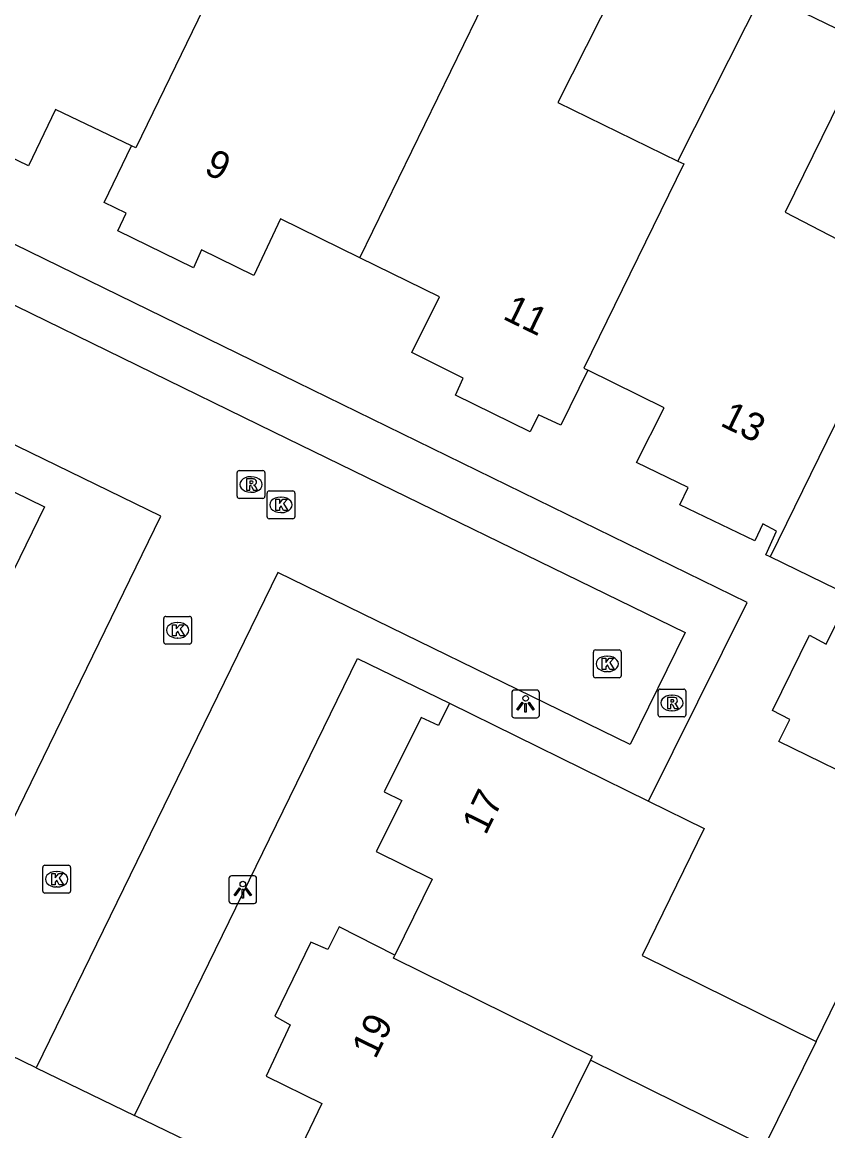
# Model space of a CAD drawing. Extents: x 159822 to 160765, y 380693 to 381634.
# Drawn here: x 160323.34 to 160352.34, y 381522.59 to 381562.51 of the extents above; entities that cross this region are included whole.
import ezdxf

# ---------------------------------------------------------------- set-up
doc = ezdxf.new("R2010")
doc.units = 0
for name, color, linetype in [('IMGEO_Kolk', 7, 'Continuous'), ('IMGEO_Lichtpunt', 7, 'Continuous'), ('IMGEO_Muur', 7, 'Continuous'), ('IMGEO_Pand', 7, 'Continuous'), ('IMGEO_Pand_nummerreeks', 7, 'Continuous'), ('IMGEO_Rijbaan_lokaal_open', 7, 'Continuous'), ('IMGEO_Rioolput', 7, 'Continuous'), ('IMGEO_Voetpad_open', 7, 'Continuous')]:
    doc.layers.add(name, color=color, linetype=linetype)

msp = doc.modelspace()

# ---------------------------------------------------------------- linework, layer by layer
at = {"layer": 'IMGEO_Kolk'}
for p, q in [((160332.157, 381544.701), (160332.157, 381545.553)), ((160332.232, 381545.627), (160333.084, 381545.627)), ((160333.158, 381545.553), (160333.158, 381544.701)), ((160332.645, 381545.407), (160332.67, 381545.407)), ((160332.668, 381544.847), (160332.643, 381544.847)), ((160333.084, 381544.627), (160332.232, 381544.627)), ((160328.513, 381541.112), (160329.365, 381541.112)), ((160328.438, 381540.186), (160328.438, 381541.038)), ((160328.926, 381540.892), (160328.951, 381540.892)), ((160329.439, 381541.038), (160329.439, 381540.186)), ((160328.949, 381540.332), (160328.924, 381540.332)), ((160329.365, 381540.112), (160328.513, 381540.112)), ((160343.979, 381539.902), (160344.831, 381539.902)), ((160343.904, 381538.976), (160343.904, 381539.828)), ((160344.392, 381539.682), (160344.417, 381539.682)), ((160344.905, 381539.828), (160344.905, 381538.976)), ((160344.415, 381539.122), (160344.39, 381539.122)), ((160344.831, 381538.902), (160343.979, 381538.902)), ((160324.083, 381531.222), (160324.083, 381532.074)), ((160324.158, 381532.148), (160325.01, 381532.148)), ((160324.571, 381531.928), (160324.596, 381531.928)), ((160325.084, 381532.074), (160325.084, 381531.222)), ((160325.01, 381531.148), (160324.158, 381531.148)), ((160324.594, 381531.368), (160324.569, 381531.368))]:
    msp.add_line(p, q, dxfattribs=at)
for points in [[(160332.157, 381544.701), (160332.157, 381545.553)], [(160332.232, 381545.627), (160333.084, 381545.627)], [(160333.158, 381545.553), (160333.158, 381544.701)], [(160332.478, 381545.327), (160332.601, 381545.327), (160332.601, 381545.176), (160332.731, 381545.327), (160332.895, 381545.327), (160332.749, 381545.176), (160332.902, 381544.927), (160332.75, 381544.927), (160332.665, 381545.091), (160332.601, 381545.024), (160332.601, 381544.927), (160332.478, 381544.927), (160332.478, 381545.327)], [(160333.084, 381544.627), (160332.232, 381544.627)], [(160328.513, 381541.112), (160329.365, 381541.112)], [(160328.438, 381540.186), (160328.438, 381541.038)], [(160328.759, 381540.812), (160328.882, 381540.812), (160328.882, 381540.661), (160329.012, 381540.812), (160329.176, 381540.812), (160329.03, 381540.661), (160329.183, 381540.412), (160329.031, 381540.412), (160328.946, 381540.576), (160328.882, 381540.509), (160328.882, 381540.412), (160328.759, 381540.412), (160328.759, 381540.812)], [(160329.439, 381541.038), (160329.439, 381540.186)], [(160329.365, 381540.112), (160328.513, 381540.112)], [(160343.979, 381539.902), (160344.831, 381539.902)], [(160343.904, 381538.976), (160343.904, 381539.828)], [(160344.225, 381539.602), (160344.348, 381539.602), (160344.348, 381539.451), (160344.478, 381539.602), (160344.642, 381539.602), (160344.496, 381539.451), (160344.649, 381539.202), (160344.497, 381539.202), (160344.412, 381539.366), (160344.348, 381539.299), (160344.348, 381539.202), (160344.225, 381539.202), (160344.225, 381539.602)], [(160344.905, 381539.828), (160344.905, 381538.976)], [(160344.831, 381538.902), (160343.979, 381538.902)], [(160324.083, 381531.222), (160324.083, 381532.074)], [(160324.158, 381532.148), (160325.01, 381532.148)], [(160325.084, 381532.074), (160325.084, 381531.222)], [(160324.404, 381531.848), (160324.527, 381531.848), (160324.527, 381531.697), (160324.657, 381531.848), (160324.821, 381531.848), (160324.675, 381531.697), (160324.828, 381531.448), (160324.676, 381531.448), (160324.591, 381531.612), (160324.527, 381531.545), (160324.527, 381531.448), (160324.404, 381531.448), (160324.404, 381531.848)], [(160325.01, 381531.148), (160324.158, 381531.148)]]:
    msp.add_lwpolyline(points, dxfattribs=at)
for centre, start, end in [((160332.234, 381545.551), 91.552, 178.448), ((160332.234, 381545.551), 91.552, 178.448), ((160333.082, 381545.551), 1.552, 88.448), ((160333.082, 381545.551), 1.552, 88.448), ((160332.234, 381544.703), 181.552, 268.448), ((160332.234, 381544.703), 181.552, 268.448), ((160333.082, 381544.703), 271.552, 358.448), ((160333.082, 381544.703), 271.552, 358.448), ((160328.515, 381541.036), 91.552, 178.448), ((160328.515, 381541.036), 91.552, 178.448), ((160329.363, 381541.036), 1.552, 88.448), ((160329.363, 381541.036), 1.552, 88.448), ((160328.515, 381540.188), 181.552, 268.448), ((160328.515, 381540.188), 181.552, 268.448), ((160329.363, 381540.188), 271.552, 358.448), ((160329.363, 381540.188), 271.552, 358.448), ((160343.981, 381539.826), 91.552, 178.448), ((160343.981, 381539.826), 91.552, 178.448), ((160344.829, 381539.826), 1.552, 88.448), ((160344.829, 381539.826), 1.552, 88.448), ((160343.981, 381538.978), 181.552, 268.448), ((160343.981, 381538.978), 181.552, 268.448), ((160344.829, 381538.978), 271.552, 358.448), ((160344.829, 381538.978), 271.552, 358.448), ((160324.16, 381532.072), 91.552, 178.448), ((160324.16, 381532.072), 91.552, 178.448), ((160325.008, 381532.072), 1.552, 88.448), ((160325.008, 381532.072), 1.552, 88.448), ((160324.16, 381531.224), 181.552, 268.448), ((160324.16, 381531.224), 181.552, 268.448), ((160325.008, 381531.224), 271.552, 358.448), ((160325.008, 381531.224), 271.552, 358.448)]:
    msp.add_arc(centre, 0.0765, start, end, dxfattribs=at)
for centre, major_axis, ratio, start_param, end_param in [((160332.644, 381545.127), (-0.387, 0.002), 0.722429, 4.712389, 7.853982), ((160332.669, 381545.127), (-0.39, 0.002), 0.717154, 1.570796, 4.712389), ((160328.925, 381540.612), (-0.387, 0.002), 0.722429, 4.712389, 7.853982), ((160328.95, 381540.612), (-0.39, 0.002), 0.717154, 1.570796, 4.712389), ((160344.391, 381539.402), (-0.387, 0.002), 0.722429, 4.712389, 7.853982), ((160344.416, 381539.402), (-0.39, 0.002), 0.717154, 1.570796, 4.712389), ((160324.57, 381531.648), (-0.387, 0.002), 0.722429, 4.712389, 7.853982), ((160324.595, 381531.648), (-0.39, 0.002), 0.717154, 1.570796, 4.712389)]:
    msp.add_ellipse(centre, major_axis=major_axis, ratio=ratio, start_param=start_param, end_param=end_param, dxfattribs=at)
at = {"layer": 'IMGEO_Lichtpunt'}
for p, q in [((160340.966, 381538.363), (160340.966, 381537.556)), ((160340.966, 381538.363), (160340.966, 381537.556)), ((160341.868, 381538.458), (160341.06, 381538.458)), ((160341.868, 381538.458), (160341.06, 381538.458)), ((160341.962, 381537.556), (160341.962, 381538.363)), ((160341.962, 381537.556), (160341.962, 381538.363)), ((160341.06, 381537.462), (160341.868, 381537.462)), ((160341.06, 381537.462), (160341.868, 381537.462)), ((160330.786, 381531.675), (160330.786, 381530.868)), ((160330.786, 381531.675), (160330.786, 381530.868)), ((160331.688, 381531.77), (160330.88, 381531.77)), ((160331.688, 381531.77), (160330.88, 381531.77)), ((160331.782, 381530.868), (160331.782, 381531.675)), ((160331.782, 381530.868), (160331.782, 381531.675)), ((160330.88, 381530.774), (160331.688, 381530.774)), ((160330.88, 381530.774), (160331.688, 381530.774))]:
    msp.add_line(p, q, dxfattribs=at)
for points in [[(160341.34, 381538.027), (160341.379, 381537.999), (160341.191, 381537.737), (160341.153, 381537.764), (160341.34, 381538.027)], [(160341.442, 381537.979), (160341.489, 381537.979), (160341.489, 381537.657), (160341.442, 381537.657), (160341.442, 381537.979)], [(160341.552, 381537.999), (160341.59, 381538.026), (160341.777, 381537.764), (160341.738, 381537.736), (160341.552, 381537.999)], [(160331.16, 381531.339), (160331.199, 381531.311), (160331.011, 381531.049), (160330.973, 381531.076), (160331.16, 381531.339)], [(160331.262, 381531.291), (160331.309, 381531.291), (160331.309, 381530.969), (160331.262, 381530.969), (160331.262, 381531.291)], [(160331.372, 381531.311), (160331.41, 381531.338), (160331.597, 381531.076), (160331.558, 381531.048), (160331.372, 381531.311)]]:
    msp.add_lwpolyline(points, dxfattribs=at)
for centre in [(160341.465, 381538.161), (160331.285, 381531.473)]:
    msp.add_circle(centre, 0.0994, dxfattribs=at)
for centre, start, end in [((160341.06, 381538.363), 90, 180), ((160341.06, 381538.363), 90, 180), ((160341.868, 381538.363), 0, 90), ((160341.868, 381538.363), 0, 90), ((160341.06, 381537.556), 180, 270), ((160341.06, 381537.556), 180, 270), ((160341.868, 381537.556), 270, 0), ((160341.868, 381537.556), 270, 360), ((160330.88, 381531.675), 90, 180), ((160330.88, 381531.675), 90, 180), ((160331.688, 381531.675), 0, 90), ((160331.688, 381531.675), 0, 90), ((160330.88, 381530.868), 180, 270), ((160330.88, 381530.868), 180, 270), ((160331.688, 381530.868), 270, 0), ((160331.688, 381530.868), 270, 360)]:
    msp.add_arc(centre, 0.0946, start, end, dxfattribs=at)
at = {"layer": 'IMGEO_Muur'}
msp.add_lwpolyline([(160351.928, 381525.801), (160354.166, 381530.406)], dxfattribs=at)
at = {"layer": 'IMGEO_Pand'}
for points in [[(160335.493, 381554.025), (160342.053, 381567.476)], [(160342.053, 381567.476), (160345.692, 381565.698), (160342.629, 381559.618), (160346.949, 381557.505)], [(160331.04, 381565.042), (160330.892, 381565.114), (160327.428, 381557.98), (160327.277, 381558.053)], [(160346.949, 381557.505), (160350.001, 381563.578), (160353.769, 381561.732), (160353.782, 381561.726), (160350.812, 381555.664), (160355.222, 381553.37)], [(160327.277, 381558.053), (160324.541, 381559.364), (160323.565, 381557.338), (160321.716, 381558.227), (160321.402, 381557.626), (160318.722, 381558.946), (160319, 381559.581), (160318.515, 381559.808), (160318.087, 381558.97), (160317.933, 381559.045)], [(160335.493, 381554.025), (160332.641, 381555.422), (160331.683, 381553.382), (160329.798, 381554.307), (160329.504, 381553.666), (160326.786, 381554.998), (160327.081, 381555.629), (160326.294, 381556.014), (160327.277, 381558.053)], [(160346.949, 381557.505), (160347.157, 381557.403), (160343.557, 381550.049), (160343.701, 381549.978)], [(160343.701, 381549.978), (160342.736, 381547.994), (160341.933, 381548.373), (160341.632, 381547.756), (160338.938, 381549.074), (160339.218, 381549.688), (160337.372, 381550.611), (160338.366, 381552.618), (160335.493, 381554.025)], [(160355.222, 381553.37), (160350.263, 381543.258)], [(160350.263, 381543.258), (160350.11, 381543.333), (160350.501, 381544.174), (160350.007, 381544.442), (160349.712, 381543.828), (160347.012, 381545.13), (160347.312, 381545.75), (160345.46, 381546.649), (160346.451, 381548.622), (160343.701, 381549.978)], [(160355.933, 381533.985), (160355.328, 381532.797), (160353.629, 381533.627), (160354.214, 381534.829), (160350.579, 381536.605), (160350.979, 381537.401), (160350.352, 381537.724), (160351.681, 381540.432), (160352.286, 381540.116), (160353.146, 381541.847), (160350.263, 381543.258)], [(160338.728, 381537.986), (160338.329, 381537.178), (160337.702, 381537.469), (160336.373, 381534.79), (160337.009, 381534.481), (160336.091, 381532.641), (160338.105, 381531.648), (160336.759, 381528.914)], [(160338.728, 381537.986), (160345.895, 381534.462)], [(160345.895, 381534.462), (160347.891, 381533.48), (160345.667, 381528.907), (160351.928, 381525.801), (160350.068, 381522.042), (160343.805, 381525.133)], [(160336.759, 381528.914), (160334.752, 381529.928), (160334.344, 381529.116), (160333.734, 381529.38), (160332.434, 381526.713), (160332.994, 381526.411), (160332.122, 381524.559), (160334.13, 381523.577), (160332.69, 381520.571)], [(160343.805, 381525.133), (160343.872, 381525.268), (160336.706, 381528.807), (160336.759, 381528.914)], [(160343.805, 381525.133), (160341.685, 381520.858), (160347.965, 381517.745), (160346.09, 381513.962)]]:
    msp.add_lwpolyline(points, dxfattribs=at)
at = {"layer": 'IMGEO_Rijbaan_lokaal_open'}
for points in [[(160319.643, 381526.897), (160328.335, 381544.714), (160315.686, 381550.873), (160317.652, 381554.951), (160332.391, 381547.759), (160347.209, 381540.529), (160345.228, 381536.493), (160332.547, 381542.69), (160323.844, 381524.858)], [(160323.844, 381524.858), (160319.643, 381526.897)]]:
    msp.add_lwpolyline(points, dxfattribs=at)
at = {"layer": 'IMGEO_Rioolput'}
for p, q in [((160331.08, 381545.434), (160331.08, 381546.286)), ((160331.155, 381546.36), (160332.007, 381546.36)), ((160332.081, 381546.286), (160332.081, 381545.434)), ((160331.568, 381546.14), (160331.593, 381546.14)), ((160331.591, 381545.58), (160331.566, 381545.58)), ((160332.007, 381545.36), (160331.155, 381545.36)), ((160346.233, 381537.567), (160346.233, 381538.419)), ((160346.308, 381538.493), (160347.16, 381538.493)), ((160347.234, 381538.419), (160347.234, 381537.567)), ((160346.721, 381538.273), (160346.746, 381538.273)), ((160347.16, 381537.493), (160346.308, 381537.493)), ((160346.744, 381537.713), (160346.719, 381537.713))]:
    msp.add_line(p, q, dxfattribs=at)
for points in [[(160331.08, 381545.434), (160331.08, 381546.286)], [(160331.155, 381546.36), (160332.007, 381546.36)], [(160332.081, 381546.286), (160332.081, 381545.434)], [(160331.669, 381546.058), (160331.417, 381546.06), (160331.417, 381545.66)], [(160331.595, 381545.979), (160331.541, 381545.979), (160331.541, 381545.898)], [(160331.541, 381545.898), (160331.593, 381545.898)], [(160331.417, 381545.66), (160331.541, 381545.66), (160331.541, 381545.822), (160331.552, 381545.822)], [(160331.599, 381545.793), (160331.67, 381545.66), (160331.81, 381545.66), (160331.745, 381545.786)], [(160332.007, 381545.36), (160331.155, 381545.36)], [(160346.233, 381537.567), (160346.233, 381538.419)], [(160346.308, 381538.493), (160347.16, 381538.493)], [(160347.234, 381538.419), (160347.234, 381537.567)], [(160346.822, 381538.191), (160346.57, 381538.193), (160346.57, 381537.793)], [(160346.57, 381537.793), (160346.694, 381537.793), (160346.694, 381537.955), (160346.705, 381537.955)], [(160346.748, 381538.112), (160346.694, 381538.112), (160346.694, 381538.031)], [(160346.694, 381538.031), (160346.746, 381538.031)], [(160346.752, 381537.926), (160346.823, 381537.793), (160346.963, 381537.793), (160346.898, 381537.919)], [(160347.16, 381537.493), (160346.308, 381537.493)]]:
    msp.add_lwpolyline(points, dxfattribs=at)
for centre, radius, start, end in [((160331.157, 381546.284), 0.0765, 91.552, 178.448), ((160331.157, 381546.284), 0.0765, 91.552, 178.448), ((160332.005, 381546.284), 0.0765, 1.552, 88.448), ((160332.005, 381546.284), 0.0765, 1.552, 88.448), ((160331.577, 381546.087), 0.19, 274.7715, 282.9687), ((160331.601, 381545.883), 0.0964, 77.0061, 93.1865), ((160331.615, 381545.94), 0.0378, 276.6634, 79.6772), ((160331.668, 381545.948), 0.109, 350.3612, 89.416), ((160331.666, 381545.948), 0.112, 277.5842, 350.9817), ((160331.551, 381545.769), 0.0533, 26.0293, 88.6989), ((160331.65, 381545.733), 0.108, 29.5134, 73.7905), ((160331.157, 381545.436), 0.0765, 181.552, 268.448), ((160331.157, 381545.436), 0.0765, 181.552, 268.448), ((160332.005, 381545.436), 0.0765, 271.552, 358.448), ((160332.005, 381545.436), 0.0765, 271.552, 358.448), ((160346.31, 381538.417), 0.0765, 91.552, 178.448), ((160346.31, 381538.417), 0.0765, 91.552, 178.448), ((160347.158, 381538.417), 0.0765, 1.552, 88.448), ((160347.158, 381538.417), 0.0765, 1.552, 88.448), ((160346.704, 381537.902), 0.0533, 26.0293, 88.6989), ((160346.73, 381538.22), 0.19, 274.7715, 282.9687), ((160346.754, 381538.016), 0.0964, 77.0061, 93.1865), ((160346.768, 381538.073), 0.0378, 276.6634, 79.6772), ((160346.821, 381538.081), 0.109, 350.3612, 89.416), ((160346.819, 381538.081), 0.112, 277.5842, 350.9817), ((160346.803, 381537.866), 0.108, 29.5134, 73.7905), ((160346.31, 381537.569), 0.0765, 181.552, 268.448), ((160346.31, 381537.569), 0.0765, 181.552, 268.448), ((160347.158, 381537.569), 0.0765, 271.552, 358.448), ((160347.158, 381537.569), 0.0765, 271.552, 358.448)]:
    msp.add_arc(centre, radius, start, end, dxfattribs=at)
for centre, major_axis, ratio, start_param, end_param in [((160331.567, 381545.86), (-0.387, 0.002), 0.722429, 4.712389, 7.853982), ((160331.592, 381545.86), (-0.39, 0.002), 0.717154, 1.570796, 4.712389), ((160346.72, 381537.993), (-0.387, 0.002), 0.722429, 4.712389, 7.853982), ((160346.745, 381537.993), (-0.39, 0.002), 0.717154, 1.570796, 4.712389)]:
    msp.add_ellipse(centre, major_axis=major_axis, ratio=ratio, start_param=start_param, end_param=end_param, dxfattribs=at)
at = {"layer": 'IMGEO_Voetpad_open'}
for points in [[(160345.895, 381534.462), (160349.444, 381541.616), (160333.242, 381549.532), (160317.168, 381557.385), (160313.61, 381550.198)], [(160320.845, 381546.663), (160324.15, 381545.059), (160316.129, 381528.616)], [(160327.383, 381523.136), (160335.409, 381539.6), (160338.728, 381537.986)], [(160323.844, 381524.858), (160327.383, 381523.136)], [(160332.69, 381520.571), (160327.383, 381523.136)]]:
    msp.add_lwpolyline(points, dxfattribs=at)

# ---------------------------------------------------------------- texts
at = {"layer": 'IMGEO_Pand_nummerreeks'}
for s, rotation, p in [('9', 333.969, (160329.847, 381557.083)), ('11', 333.9931, (160340.601, 381551.84)), ('13', 333.8502, (160348.432, 381547.998)), ('17', 63.7402, (160340.025, 381533.203)), ('19', 63.9021, (160336.059, 381525.14))]:
    msp.add_text(s, height=1, rotation=rotation, dxfattribs=at).set_placement(p)

doc.saveas('drawing.dxf')
